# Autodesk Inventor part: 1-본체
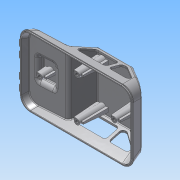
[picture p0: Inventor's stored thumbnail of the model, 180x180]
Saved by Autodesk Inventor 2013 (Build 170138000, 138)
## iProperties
Created: 2015-05
Part Number: 1-본체
Material: ABS 플라스틱
Document SubType Name: Modeling
Designer: Administrator
Density: 7.85 g/cm^3
Mass: 233.902 g
Surface Area: 305.679 cm^2
Volume: 29.7964 cm^3
Author: Administrator
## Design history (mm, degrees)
sketch "스케치1"
  geometry: L1 (0, 0)-(122, 0); L2 (42, 11.089)-(54.442, 31); L3 (54.442, 31)-(92, 31); L4 (92, 31)-(122, 11); L5 (118.738, 13.175)-(122, 1); L6 (2.144, 9)-(42, 11.089); L7 (122, 1)-(122, 0); L8 (0, 0)-(0, 1); L9 (0, 1)-(2.144, 9); L10 (0, 1)-(50, 1); L11 (0, 0)-(1, 0); L12 (1, 0)-(1, 1); L13 (1, 1)-(0, 1); L14 (0, 1)-(0, 0); L15 (122, 0)-(121, 0); L16 (121, 0)-(121, 1); L17 (121, 1)-(122, 1); L18 (122, 1)-(122, 0); L19 (122, 1)-(122, 13)
  constraints: 38 end point, 6 parallel, 3 horizontal, 3 perpendicular, 3 point on line, 1 collinear, 1 vertical
  dimensions: "d0" = 122 distance of L1.start L1.end; "d5" = 42 horizontal distance of L1.start L2.start; "d6" = 9 vertical distance of L1.start L6.start; "d7" = 125 deg angle of L2 L6; "d9" = 105 deg angle of L1 L5; "d19" = 1 distance of L1.start L8.end; "d20" = 1 distance of L5.end L1.end; "d21" = 105 deg angle of L1 L9; "d23" = 3 deg angle of L10 L6; "d24" = 1 distance of L1.start L11.end; "d25" = 1 distance of L15.end L16.end; "d26" = 1 distance of L16.end L17.end; "d70" = 30 horizontal distance of L5.end L3.end; "d76" = 31 distance between parallel lines of L1 L3; "d77" = 20 vertical distance of L3.end L4.end
extrude "돌출1" new body sketch "스케치1" stored distance "d15" = 76; taper "d16" = 0 deg
sketch "스케치3"
  geometry: L1 (13.175, 38)-(31, 38) reference; L2 (1, 38)-(13.175, 38) reference; L3 (31, -38)-(13.175, -38) reference; L4 (13.175, -38)-(1, -38) reference; L5 (31, -38)-(31, 38) reference; L6 (0, 38)-(1, 38) reference; L7 (1, -38)-(0, -38) reference; L8 (0, 38)-(1, 38); L9 (0, -38)-(1, -38); L10 (1, 38)-(31, 38); L11 (31, 38)-(31, 29.962); L12 (31, -29.962)-(31, -38); L13 (31, -38)-(1, -38); L14 (1, -38)-(1, 38) reference; L15 (31, -29.962)-(1, -38); L16 (31, 29.962)-(1, 38); 1 further point
  constraints: 16 end point, 3 collinear, 2 horizontal, 2 point on line
  dimensions: "d38" = 105 deg angle of L14 L16; "d39" = 15 deg angle of L3 L15; "d40" = 7.76457 distance from line of L1.end L16; "d41" = 65.64579 distance from line of L1.end L15
extrude "돌출3" cut sketch "스케치3" stored distance "d36" = 0; taper "d37" = 0 deg
fillet "모깎기1" dims "d42" = 12, "d44" = 3
fillet "모깎기2" dims "d45" = 3
sketch "스케치7"
  geometry: L1 (40.44, 11.007)-(13.137, 9.576) reference; L2 (10.985, 9.463)-(12.541, 14.552); L3 (12.541, 14.552)-(28.878, 15.408); L4 (28.878, 15.408)-(30.958, 10.51); L5 (10.985, 9.463)-(30.958, 10.51); L6 (4.32, 9.114)-(13.137, 9.576) reference; L7 (4.32, 9.114)-(-6, 8.573); L8 (0, 0)-(0, 8.888)
  constraints: 12 end point, 3 point on line, 1 collinear, 1 parallel, 1 vertical
  dimensions: "d59" = 70 deg angle of L1 L4; "d61" = 11 distance of L2.start L8.end; "d63" = 20 distance of L2.start L4.end; "d64" = 5 distance between parallel lines of L1 L3; "d101" = 70 deg angle of L6 L2
extrude "돌출4" join sketch "스케치7" stored distance "d65" = 26; taper "d66" = 0 deg
node "작업 평면1"
sketch "스케치15"
  geometry: L1 (13, 5)-(-13, 5) reference; L2 (-13, 0)-(-13, 5) reference; L3 (13, 5)-(13, 0) reference; L4 (-13, 0)-(-11.18, 5); L5 (-13, 5)-(-11.18, 5); L6 (-13, 5)-(-13, 0); L7 (11.18, 5)-(13, 0); L8 (13, 5)-(11.18, 5); L9 (13, 5)-(13, 0); L10 (24.829, 0)-(-24.829, 0) reference; 1 further point
  constraints: 12 end point, 3 collinear, 2 point on line, 1 perpendicular
  dimensions: "d108" = 70 deg angle of L10 L7; "d109" = 70 deg angle of L10 L4
extrude "돌출8" cut sketch "스케치15" distance "d110" = 35; taper "d111" = 0 deg
fillet "모깎기11" dims "d112" = 3
fillet "모깎기12" dims "d113" = 3
feature "쉘1" dims "d46" = 2
sketch "스케치5"
  geometry: L1 (53.253, 11)-(78.84, 11); L2 (81.84, 14)-(81.84, 23); L3 (78.84, 26)-(58.876, 26); L4 (56.332, 24.59)-(50.708, 15.59); L5 (91.092, 31)-(56.105, 31) reference; L6 (53.561, 29.59)-(42.828, 12.413) reference; L7 (107.213, 20.858)-(92.756, 30.496) reference; L8 (87.986, 11)-(103.078, 11); L9 (104.742, 16.496)-(91.242, 25.496); L10 (89.578, 26)-(87.986, 26); L11 (84.986, 23)-(84.986, 14); A1 r 3 centre (56.105, 28) between (56.105, 31) and (53.561, 29.59) reference; A2 r 3 centre (58.876, 23) between (58.876, 26) and (56.332, 24.59); A3 r 3 centre (78.84, 23) between (81.84, 23) and (78.84, 26); A4 r 3 centre (78.84, 14) between (78.84, 11) and (81.84, 14); A5 r 3 centre (53.253, 14) between (50.708, 15.59) and (53.253, 11); A6 r 3 centre (89.578, 23) between (91.242, 25.496) and (89.578, 26); A7 r 3 centre (87.986, 23) between (87.986, 26) and (84.986, 23); A8 r 3 centre (87.986, 14) between (84.986, 14) and (87.986, 11); A9 r 3 centre (103.078, 14) between (103.078, 11) and (104.742, 16.496); 5 further points
  constraints: 16 end point, 16 point on circle, 16 tangent, 9 point on line, 8 centre point, 7 equal radius, 5 parallel, 2 perpendicular, 1 collinear, 1 horizontal
  dimensions: "d47" = 5 distance between parallel lines of L3 L5; "d48" = 5 distance between parallel lines of L6 L4; "d50" = 34 distance of point (47.84, 11) point (81.84, 11); "d53" = 28 distance of point (112.986, 11) point (84.986, 11); "d54" = 5 distance between parallel lines of L9 L7; "d55" = 15 distance between parallel lines of L1 L3; "d56" = 5 distance between parallel lines of L5 L10; "d78" = 3 radius of A2
extrude "돌출5" cut sketch "스케치5" stored distance "d79" = 26; taper "d80" = 0 deg
sketch "스케치11"
  geometry: L1 (0, -2)-(98, -2) reference; L2 (0, 0)-(98, 0) reference; L3 (-12, -12)-(-12, -64) reference; L4 (98, -76)-(0, -76) reference; L5 (110, -64)-(110, -12) reference; L6 (109, -12)-(109, -64); L7 (98, -75)-(0, -75); L8 (-11, -64)-(-11, -12); L9 (0, -1)-(98, -1); A1 r 12 centre (98, -12) between (110, -12) and (98, 0) reference; A2 r 12 centre (0, -12) between (0, 0) and (-12, -12) reference; A3 r 12 centre (0, -64) between (-12, -64) and (0, -76) reference; A4 r 12 centre (98, -64) between (98, -76) and (110, -64) reference; A5 r 11 centre (98, -12) between (109, -12) and (98, -1); A6 r 11 centre (98, -64) between (98, -75) and (109, -64); A7 r 11 centre (0, -64) between (-11, -64) and (0, -75); A8 r 11 centre (0, -12) between (0, -1) and (-11, -12); 1 further point
  constraints: 8 end point, 8 point on circle, 4 centre point, 7 other
  dimensions: "d82" = 1 distance between parallel lines of L1 L9
extrude "돌출6" cut sketch "스케치11" distance "d83" = 1; taper "d84" = 0 deg
sketch "스케치12"
  geometry: L1 (-12, -64)-(-12, -12) reference; L2 (110, -64)-(110, -12) reference; C1 r 3 at (49, -16); C2 r 3 at (89, -38); C3 r 3 at (9, -38); C4 r 3 at (49, -60); 3 further points
  constraints: 4 centre point, 3 equal radius, 2 horizontal alignment, 2 midpoint, 1 vertical alignment
  dimensions: "d85" = 6 diameter of C1; "d87" = 22 vertical distance of point (-12, -38) C1.centre; "d88" = 21 distance from line of L2 C2.centre; "d90" = 40 horizontal distance of C1.centre C2.centre; "d91" = 40 horizontal distance of C3.centre C1.centre; "d92" = 22 vertical distance of point (-12, -38) C4.centre (= d87)
extrude "돌출7" join sketch "스케치12" stored distance "d93" = 1; taper "d94" = 2 deg
node "작업 평면2"
sketch "스케치16"
  geometry: L1 (-5, 1)-(5, 1); L2 (5, 1)-(5, -1); L3 (5, -1)-(-5, -1); L4 (-5, -1)-(-5, 1); L5 (-5, 1)-(5, -1); L6 (5, 1)-(-5, -1); L7 (-5, 45)-(5, 45); L8 (5, 45)-(5, 43); L9 (5, 43)-(-5, 43); L10 (-5, 43)-(-5, 45); L11 (-5, 45)-(5, 43); L12 (5, 45)-(-5, 43); L13 (35, 23)-(45, 23); L14 (45, 23)-(45, 21); L15 (45, 21)-(35, 21); L16 (35, 21)-(35, 23); L17 (35, 23)-(45, 21); L18 (45, 23)-(35, 21); L19 (-45, 23)-(-35, 23); L20 (-35, 23)-(-35, 21); L21 (-35, 21)-(-45, 21); L22 (-45, 21)-(-45, 23); L23 (-45, 23)-(-35, 21); L24 (-35, 23)-(-45, 21); C1 r 3 at (0, 44) reference; C2 r 3 at (40, 22) reference; C3 r 3 at (-40, 22) reference; C4 r 3 at (0, 0) reference; 1 further point
  constraints: 48 end point, 8 midpoint, 8 parallel, 4 horizontal, 4 perpendicular
  dimensions: "d115" = 10 distance of L1.start L1.end; "d117" = 2 distance of L1.end L2.end; "d118" = 10 horizontal distance of L19.end L21.end; "d119" = 2 distance of L19.end L20.end; "d120" = 10 distance of L8.end L9.end; "d121" = 2 distance of L7.end L8.end; "d122" = 10 distance of L13.start L13.end; "d123" = 2 distance of L13.end L14.end
extrude "돌출9" join sketch "스케치16" stored distance "d124" = 35; taper "d125" = 2.5 deg
hole "구멍1" diameter "d128" = 3.242; stored, may be unused: countersink angle "d132" = 90 deg, drill point angle "d134" = 118 deg; dims "d126" = 10, "d127" = 10, "d129" = 9, "d130" = 4, "d131" = 2, "d133" = 11
hole "구멍2" diameter "d137" = 3.242; stored, may be unused: countersink angle "d141" = 90 deg, drill point angle "d143" = 118 deg; dims "d135" = 10, "d136" = 10, "d138" = 9, "d139" = 4, "d140" = 2, "d142" = 11
hole "구멍3" diameter "d146" = 3.242; stored, may be unused: countersink angle "d150" = 90 deg, drill point angle "d152" = 118 deg; dims "d144" = 10, "d145" = 10, "d147" = 9, "d148" = 4, "d149" = 2, "d151" = 11
hole "구멍4" diameter "d155" = 3.242; stored, may be unused: countersink angle "d159" = 90 deg, drill point angle "d161" = 118 deg; dims "d153" = 10, "d154" = 10, "d156" = 9, "d157" = 4, "d158" = 2, "d160" = 11
sketch "스케치18"
  geometry: A1 r 4 centre (1, -21) between (1, -25) and (1, -17); A2 r 4 centre (1, -10) between (1, -14) and (1, -6); A3 r 4 centre (1, 10) between (1, 6) and (1, 14); A4 r 4 centre (1, 21) between (1, 17) and (1, 25); 3 further points
  constraints: 8 point on circle, 4 centre point, 3 equal radius, 13 other
  dimensions: "d162" = 10 vertical distance of A2.centre point (0, 0); "d163" = 11 distance of A1.centre A2.centre; "d164" = 10 vertical distance of point (0, 0) A3.centre (derived); "d165" = 11 distance of A3.centre A4.centre; "d167" = 4 radius of A1
extrude "돌출10" join sketch "스케치18" distance "d168" = 2; taper "d170" = 0 deg; dims "d169" = 1, "d171" = 0
chamfer "모따기1" distance "d172" = 1; stored, may be unused: second distance "d173" = 2, angle "d174" = 45 deg
sketch "스케치19"
  geometry: L1 (34.987, 55.319)-(34.987, 0) reference; L2 (65.895, 53.66)-(65.895, 1.66) reference; 3 further points
  constraints: 1 horizontal alignment, 1 midpoint, 1 other
  dimensions: "d175" = 50 distance from line of point (15.895, 27.66) L2
feature "엠보싱1" sketch "스케치19" dims "d0" = 122, "d5" = 42, "d6" = 9, "d7" = 125 deg, "d9" = 105 deg, "d19" = 1, "d20" = 1, "d21" = 105 deg, "d23" = 3 deg, "d24" = 1, "d25" = 1, "d26" = 1, "d70" = 30, "d76" = 31, "d77" = 20, "d176" = 0.5, "d177" = 0
node "솔리드1"
node "투영된 루프2"
node "투영된 루프3"
node "투영된 루프4"
other parameters: "d106" = 90 deg, "d114" = -2
